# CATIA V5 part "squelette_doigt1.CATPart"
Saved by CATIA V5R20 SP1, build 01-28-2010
Part number: squelette_doigt1
Publications: "Droite.1", "Plan.2", "Droite.3", "Droite.2"
Bounding box of the stored display mesh (mm): x -20 to 20, y 100.242 to 127.124, z 70.218 to 89.862
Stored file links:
  C:\Users\Fox\Desktop\IAO Projet\A RENDRE\Sauvegarde IFMA\squelette_doigt1.CATPart
  C:\Users\Fox\Desktop\IAO Projet\A RENDRE\Sauvegarde IFMA\squelette.CATProduct
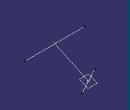
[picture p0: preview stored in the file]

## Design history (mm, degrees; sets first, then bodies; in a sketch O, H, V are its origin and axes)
Set1
  Line1: type PtPt, FirstPoint Point1, SecondPoint Point2
  Line2: type Angle, RefPoint Point2, Curve Line1, Support Plane2, Start -10, End 10, Angle 90
  Line3: type Normal, RefPoint Point1, RefSkin Plane2, Start -20, End 20
  Plane1: type Normal, Curve Line2, RefPoint Point2
Set2
  Point1: linked copy from another document
  Point2: linked copy from another document
  Plane2: linked copy from another document
Body1 (main body)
